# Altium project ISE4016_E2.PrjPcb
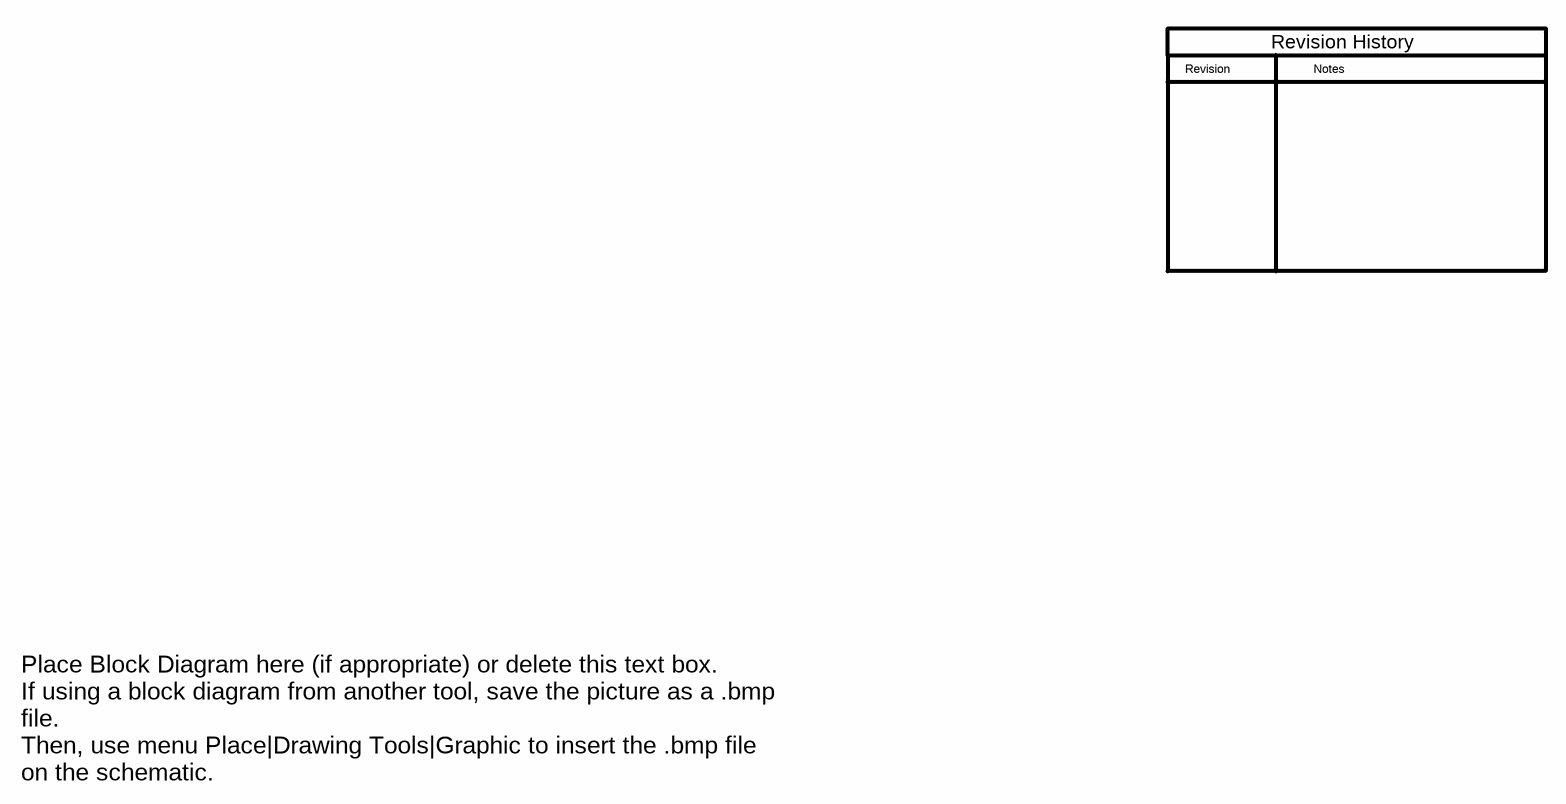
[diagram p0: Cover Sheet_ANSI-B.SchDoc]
TechSupport: http://www.ti.com/support; SCH_Rev: E2; PRJ_Title: ISE4016; PRJ_Number: ISE4016; PRJ_Engineer: Ajinder Singh; PRJ_Customer: Public Release; PCB_Rev: E2; PCB_Layout: Krypton Solutions; CopyrightYear: 2014
5 sheets, 111 parts. Net scope: global (net labels, ports and power ports of the same name join across sheets).
Board file: ISE4016_E2.PcbDoc
Sheets:
  Cover Sheet_ANSI-B.SchDoc
  BlankSheet_ANSI-B.SchDoc
  Hardware_ANSI-B.SchDoc
  Power.SchDoc
  Analog and EP.SchDoc

## Sheet Cover Sheet_ANSI-B.SchDoc
size 431 x 279 mm; Date: Not shown in title block; ApprovedBy: Not shown in title block; CheckedBy: Not shown in title block; Author: Not shown in title block; CompanyName: Not shown in title block; Engineer: Not shown in title block; Organization: Not shown in title block; Address1: Not shown in title block; Address2: Not shown in title block; Address3: Not shown in title block; Address4: Not shown in title block; DocumentNumber: 1; Revision: Use project parameter SCH_Rev; SheetNumber: 1; SheetTotal: 1; PageSetup: Record=PageOptions|CenterHorizontal=True|CenterVertical=True|PrintScale=1.00|XCorrection=1.00|YCorrection=1.00|PrintKind=0|BorderSize=5000000|LeftOffset=0|BottomOffset=0|Orientation=2|PaperLength=1000|PaperWidth=1000|Scale=100|PaperSource=15|PrintQuality=600|MediaType=1|DitherType=10|PaperKind=Letter|PrintScaleMode=1

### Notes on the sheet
- Revision
- Notes
- Revision History
- Place Block Diagram here (if appropriate) or delete this text box.
  If using a block diagram from another tool, save the picture as a .bmp file.
  Then, use menu Place|Drawing Tools|Graphic to insert the .bmp file on the schematic.

## Sheet BlankSheet_ANSI-B.SchDoc
size 431 x 279 mm; Date: Not shown in title block; ApprovedBy: Not shown in title block; CheckedBy: Not shown in title block; Author: Not shown in title block; CompanyName: Not shown in title block; Engineer: Not shown in title block; Organization: Not shown in title block; Address1: Not shown in title block; Address2: Not shown in title block; Address3: Not shown in title block; Address4: Not shown in title block; DocumentNumber: 1; Revision: Use project parameter SCH_Rev; SheetNumber: 1; SheetTotal: 1; PageSetup: Record=PageOptions|CenterHorizontal=True|CenterVertical=True|PrintScale=1.00|XCorrection=1.00|YCorrection=1.00|PrintKind=0|BorderSize=5000000|LeftOffset=0|BottomOffset=0|Orientation=2|PaperLength=1000|PaperWidth=1000|Scale=100|PaperSource=15|PrintQuality=600|MediaType=1|DitherType=10|PaperKind=Letter|PrintScaleMode=1

## Sheet Hardware_ANSI-B.SchDoc
size 431 x 279 mm; Date: Not shown in title block; ApprovedBy: Not shown in title block; CheckedBy: Not shown in title block; Author: Not shown in title block; CompanyName: Not shown in title block; Engineer: Not shown in title block; Organization: Not shown in title block; Address1: Not shown in title block; Address2: Not shown in title block; Address3: Not shown in title block; Address4: Not shown in title block; DocumentNumber: 1; Revision: Use project parameter SCH_Rev; SheetNumber: 1; SheetTotal: 1; PageSetup: Record=PageOptions|CenterHorizontal=True|CenterVertical=True|PrintScale=1.00|XCorrection=1.00|YCorrection=1.00|PrintKind=0|BorderSize=5000000|LeftOffset=0|BottomOffset=0|Orientation=2|PaperLength=1000|PaperWidth=1000|Scale=100|PaperSource=15|PrintQuality=600|MediaType=1|DitherType=10|PaperKind=Letter|PrintScaleMode=1
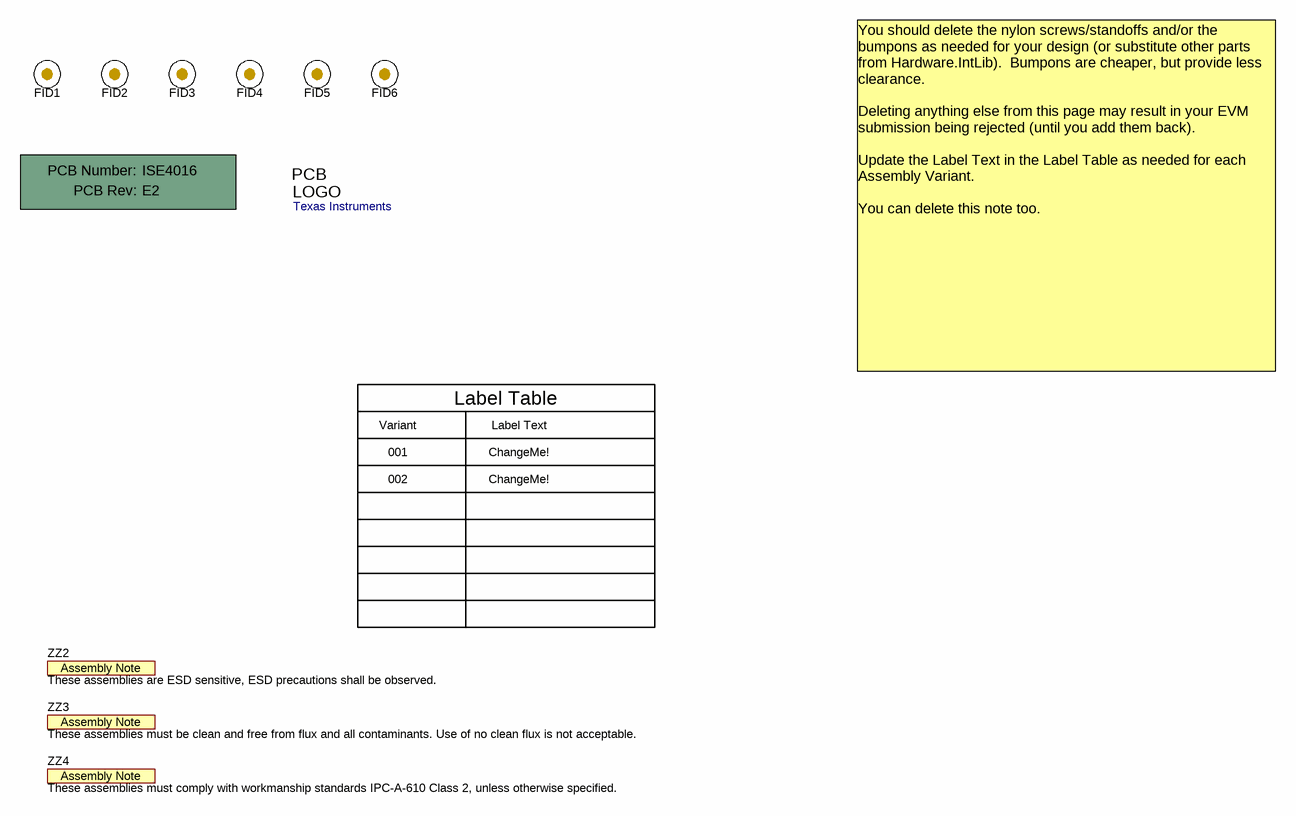
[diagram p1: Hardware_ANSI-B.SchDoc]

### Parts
!PCB1  Printed Circuit Board  (value not drawn)  (mechanical)
FID1  Fiducial  [Fiducial10-20]  (value not drawn)
FID2  Fiducial  [Fiducial10-20]  (value not drawn)
FID3  Fiducial  [Fiducial10-20]  (value not drawn)
FID4  Fiducial  [Fiducial10-20]  (value not drawn)
FID5  Fiducial  [Fiducial10-20]  (value not drawn)
FID6  Fiducial  [Fiducial10-20]  (value not drawn)
Logo1  Texas Instruments  [TI_Stacked_Overlay_Medium]  (no BOM)
ZZ2  These assemblies are ESD sensitive, ESD precautions shall be observed.  [AssemblyNote]  (no BOM)
ZZ3  These assemblies must be clean and free from flux and all contaminants. Use of no clean flux is not acceptable.  [AssemblyNote]  (no BOM)
ZZ4  These assemblies must comply with workmanship standards IPC-A-610 Class 2, unless otherwise specified.  [AssemblyNote]  (no BOM)

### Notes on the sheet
- Variant
- Label Table
- Label Text
- You should delete the nylon screws/standoffs and/or the bumpons as needed for your design (or substitute other parts from Hardware.IntLib).  Bumpons are cheaper, but provide less clearance.
  Deleting anything else from this page may result in your EVM submission being rejected (until you add them back).
  Update the Label Text in the Label Table as needed for each Assembly Variant.
  You can delete this note too.
- 001
- 002
- ChangeMe!

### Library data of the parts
!PCB1 = PCB: Manufacturer: Any; PartNumber: ISE4016; SymbolCreator: a0412235
FID1-FID6 = Fiducial: Fiducial mark.  There is nothing to buy or mount.; SymbolCreator: codlsc
Logo1 = TI_Logo: Texas Instrument Corporate Signature; SymbolCreator: a0412235
ZZ2-ZZ4 = AssemblyNote: SymbolCreator: codlsc

## Sheet Power.SchDoc
size 431 x 279 mm; Date: Not shown in title block; ApprovedBy: Not shown in title block; CheckedBy: Not shown in title block; Author: Not shown in title block; CompanyName: Not shown in title block; Engineer: Not shown in title block; Organization: Not shown in title block; Address1: Not shown in title block; Address2: Not shown in title block; Address3: Not shown in title block; Address4: Not shown in title block; DocumentNumber: 1; Revision: Use project parameter SCH_Rev; SheetNumber: 1; SheetTotal: 1; PageSetup: Record=PageOptions|CenterHorizontal=True|CenterVertical=True|PrintScale=0.96|XCorrection=1.00|YCorrection=1.00|PrintKind=0|BorderSize=5000000|LeftOffset=0|BottomOffset=0|Orientation=2|PaperLength=1000|PaperWidth=1000|Scale=100|PaperSource=15|PrintQuality=600|MediaType=1|DitherType=10|PaperKind=11x17|PrintScaleMode=1
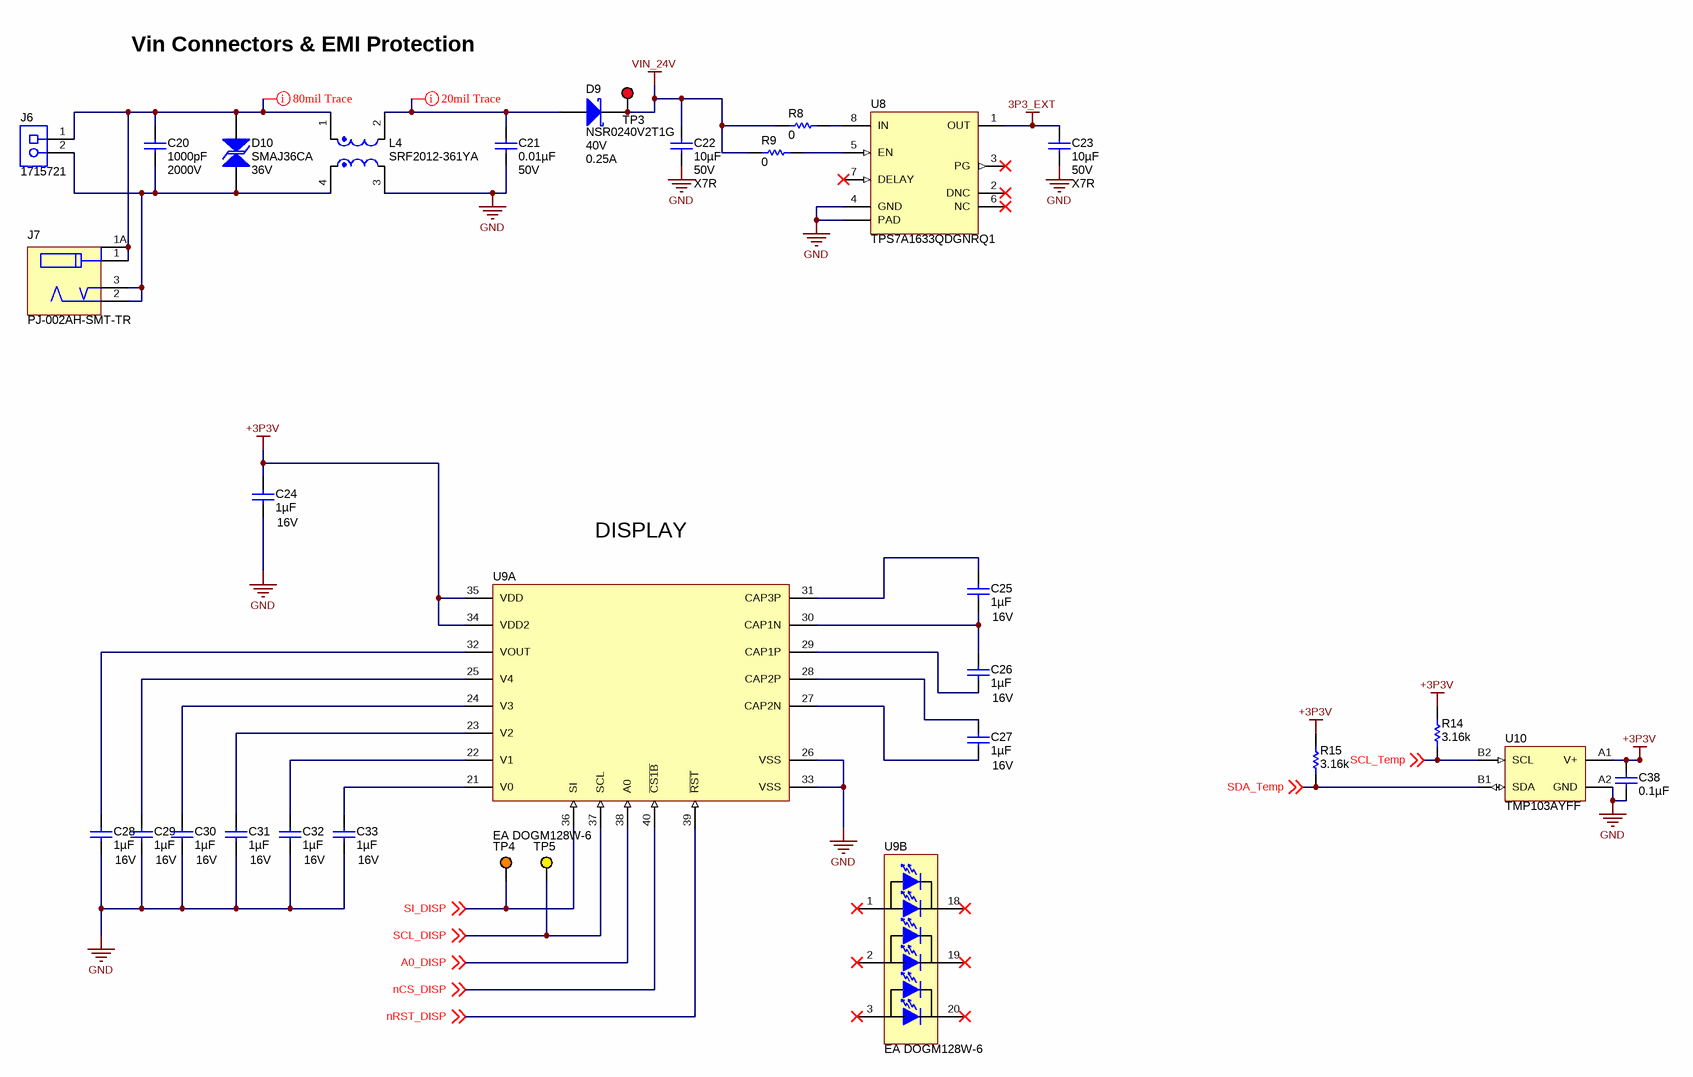
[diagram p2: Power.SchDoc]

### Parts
C20  ValueDisplayed: 1000pF  Value2: 2000V  [1210]  (hidden comment: C1210C102KGRACTU)
C21  ValueDisplayed: 0.01µF  Value2: 50V  [0402]  (hidden comment: GCM155R71H103KA55D)
C22  ValueDisplayed: 10µF  Value2: 50V  TempCo: X7R  [1210]  (hidden comment: GRM32ER71H106KA12L)
C23  ValueDisplayed: 10µF  Value2: 50V  TempCo: X7R  [1210]  (hidden comment: GRM32ER71H106KA12L)
C24  ValueDisplayed: 1µF  Value2: 16V  [0603]  (hidden comment: C1608X7R1C105K)
C25  ValueDisplayed: 1µF  Value2: 16V  [0603]  (hidden comment: C1608X7R1C105K)
C26  ValueDisplayed: 1µF  Value2: 16V  [0603]  (hidden comment: C1608X7R1C105K)
C27  ValueDisplayed: 1µF  Value2: 16V  [0603]  (hidden comment: C1608X7R1C105K)
C28  ValueDisplayed: 1µF  Value2: 16V  [0603]  (hidden comment: C1608X7R1C105K)
C29  ValueDisplayed: 1µF  Value2: 16V  [0603]  (hidden comment: C1608X7R1C105K)
C30  ValueDisplayed: 1µF  Value2: 16V  [0603]  (hidden comment: C1608X7R1C105K)
C31  ValueDisplayed: 1µF  Value2: 16V  [0603]  (hidden comment: C1608X7R1C105K)
C32  ValueDisplayed: 1µF  Value2: 16V  [0603]  (hidden comment: C1608X7R1C105K)
C33  ValueDisplayed: 1µF  Value2: 16V  [0603]  (hidden comment: C1608X7R1C105K)
C38  ValueDisplayed: 0.1µF  [0603]  (hidden comment: 06033C104JAT2A)
D9  NSR0240V2T1G  value 40V  Value1: 0.25A  [SOD-523]
D10  SMAJ36CA  value 36V  [SMA]
J6  1715721  [PhoenixContact_1715721]
J7  PJ-002AH-SMT-TR  [CUI_PJ-002AH-SMT]
L4  SRF2012-361YA  [SRF2012A]
R8  value 0  [0402]  (hidden comment: ERJ-2GE0R00X)
R9  value 0  [0402]  (hidden comment: ERJ-2GE0R00X)
R14  value 3.16k  [0603]  (hidden comment: CRCW06033K16FKEA)
R15  value 3.16k  [0603]  (hidden comment: CRCW06033K16FKEA)
TP3  5000  [Keystone5000]  (value not drawn)
TP4  5003  [Keystone5003]  (value not drawn)
TP5  5004  [Keystone5004]  (value not drawn)
U8  TPS7A1633QDGNRQ1  [DGN0008C_N]
U9  EA DOGM128W-6  [LCD-MODULE_EA DOGM128W-6]  (parts A,B of 2)
U10  TMP103AYFF  [YFF0004AAAA]

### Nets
3P3_EXT: C23.1 U8.1(OUT)
+3P3V: C24.1 C38.1 R14.2 R15.2 U9.34(VDD2) U9.35(VDD) U10.A1(V+)
GND: C21.2 C22.2 C23.2 C24.2 C28.2 C29.2 C30.2 C31.2 C32.2 C33.2 C38.2 L4.3 U8.4(GND) U8.9(PAD) U9.26(VSS) U9.33(VSS) U10.A2(GND)
VIN_24V: C22.1 D9.1(K) R8.1 R9.1 TP3.1
A0_DISP: U9.38(A0) ; off-sheet A0_DISP
nCS_DISP: U9.40(~{CS1B}) ; off-sheet nCS_DISP
nRST_DISP: U9.39(~{RST}) ; off-sheet nRST_DISP
SCL_DISP: TP5.1 U9.37(SCL) ; off-sheet SCL_DISP
SCL_Temp: R14.1 U10.B2(SCL) ; off-sheet SCL_Temp
SDA_Temp: R15.1 U10.B1(SDA) ; off-sheet SDA_Temp
SI_DISP: TP4.1 U9.36(SI) ; off-sheet SI_DISP
NetC20_1: C20.1 D10.2 J6.1 J7.1 J7.1A L4.1
NetC20_2: C20.2 D10.1 J6.2 J7.2 J7.3 L4.4
NetC21_1: C21.1 D9.2(A) L4.2
NetC25_1: C25.1 U9.31(CAP3P)
NetC25_2: C25.2 C26.1 U9.30(CAP1N)
NetC26_2: C26.2 U9.29(CAP1P)
NetC27_1: C27.1 U9.28(CAP2P)
NetC27_2: C27.2 U9.27(CAP2N)
NetC28_1: C28.1 U9.32(VOUT)
NetC29_1: C29.1 U9.25(V4)
NetC30_1: C30.1 U9.24(V3)
NetC31_1: C31.1 U9.23(V2)
NetC32_1: C32.1 U9.22(V1)
NetC33_1: C33.1 U9.21(V0)
NetR8_2: R8.2 U8.8(IN)
NetR9_2: R9.2 U8.5(EN)

Not connected (* = marked no-connect by the designer): U8 2(DNC)* 3(PG)* 6(NC)* 7(DELAY)*; U9 1(A)* 2(A)* 3(A)* 18(K)* 19(K)* 20(K)*

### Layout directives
rule Width Constraint [Pref Width = 80mil    Min Width = 80mil    Max Width = 80mil]: NetC20_1
rule Undefined; rule Width Constraint [Pref Width = 20mil    Min Width = 20mil    Max Width = 20mil]: NetC21_1

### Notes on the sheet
- Vin Connectors & EMI Protection
- DISPLAY

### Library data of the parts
C20 = C1210C102KGRACTU: CAP, CERM, 1000pF, 2000V, +/-10%, X7R, 1210; Manufacturer: Kemet; Polarized: N; CompType: Capacitor; U/M: EA; Cap_F: 0.000000001; Tolerance_%: 10; Value1: Unknown; VDC_V: 2000; TaMin_C: -55; TaMax_C: 125
C21 = GCM155R71H103KA55D: CAP, CERM, 0.01uF, 50V, +/-10%, C0G/NP0, 0402; Manufacturer: MuRata; Polarized: N; CompType: Capacitor; U/M: EA; Cap_F: 0.00000001; Tolerance_%: 10; Value1: Unknown; VDC_V: 50; TaMin_C: -55; TaMax_C: 125
C22 C23 = GRM32ER71H106KA12L: CAP, CERM, 10uF, 50V, +/-10%, X7R, 1210; Manufacturer: MuRata; Polarized: N; CompType: Capacitor; U/M: EA; Cap_F: 0.00001; Tolerance_%: 10; Value1: Unknown; VDC_V: 50; TaMin_C: -55; TaMax_C: 125
C24-C33 = C1608X7R1C105K: CAP, CERM, 1uF, 16V, +/-10%, X7R, 0603; Manufacturer: TDK; Polarized: N; CompType: Capacitor; U/M: EA; Cap_F: 0.000001; Tolerance_%: 10; ESR_Ohm: 0.0057; Value1: 0.0057 ohm; VDC_V: 16; TaMin_C: -55; TaMax_C: 125
C38 = 06033C104JAT2A: CAP, CERM, 0.1uF, 25V, +/-5%, X7R, 0603; Manufacturer: AVX; Polarized: N; CompType: Capacitor; U/M: EA; Cap_F: 0.0000001; Tolerance_%: 5; ESR_Ohm: 0.05; Value1: 0.05 ohm; VDC_V: 25; TaMin_C: -55; TaMax_C: 125
D9 = NSR0240V2T1G: Diode, Schottky, 40V, 0.25A, SOD-523; Manufacturer: ON Semiconductor; U/M: EA; Vf_V: 0.7; Value2: 0.7V; Io_A: 0.25; Vr_V: 40; TJmax_C: 150; RJC_CperW: 600
D10 = SMAJ36CA: Diode, TVS, Bi, 36V, 400W, SMA; Manufacturer: Littelfuse; U/M: EA; Power_W: 400; Vr_V: 36; RJA_CperW: 120
J6 = 1715721: Conn Term Block, 2POS, 5.08mm, TH; Manufacturer: Phoenix Contact; SymbolCreator: a0412235; Value: 2x1; CompType: Terminal Block; U/M: EA
J7 = PJ-002AH-SMT-TR: Power Jack, SMT; Manufacturer: CUI Inc.; SymbolCreator: a0411947; U/M: EA
L4 = SRF2012-361YA: Inductor, Wirewound, Ferrite, , 0.3A, 0.45 ohm, SMD; Manufacturer: Bourns; SymbolCreator: a0411947; Imax_A: 0.3; DCR_ohm: 0.45; ZTyp@100MHz_Ohm: 360; U/M: EA
R8 R9 = ERJ-2GE0R00X: RES, 0 ohm, 5%, 0.063W, 0402; Manufacturer: Panasonic; CompType: Resistor; Value_Code: 0000; Tolerance_%: 5; Power_W: 0.063; VDC_V: 50; TempCo: 600 ppm/C; EIA_Code: E24; U/M: EA
R14 R15 = CRCW06033K16FKEA: RES, 3.16k ohm, 1%, 0.1W, 0603; Manufacturer: Vishay-Dale; CompType: Resistor; Res_ohm: 3160; Value_Code: 3k16; Tolerance_%: 1; Power_W: 0.1; VDC_V: 75; TempCo: 100 ppm/C; EIA_Code: E96; U/M: EA
TP3 = 5000: Test Point, Miniature, Red, TH; Manufacturer: Keystone; CompType: Test Point Loop; U/M: EA
TP4 = 5003: Test Point, Miniature, Orange, TH; Manufacturer: Keystone; CompType: Test Point Loop; U/M: EA
TP5 = 5004: Test Point, Miniature, Yellow, TH; Manufacturer: Keystone; CompType: Test Point Loop; U/M: EA
U8 = TPS7A1633QDGNRQ1: 60-V, 5-µA IQ, 100-mA, Low-Dropout VOLTAGE REGULATOR With Enable and Power-Good, DGN0008C; Alternate Manufacturer: None; Manufacturer: Texas Instruments; SymbolCreator: a0411947; CompType: IC; U/M: EA
U9 = EA DOGM128W-6: Module, 128x64-pixel graphics display; Manufacturer: Electronic Assembly; SymbolCreator: a0799628
U10 = TMP103AYFF: Low-Power, Digital Temperature Sensor with Two-Wire Interface in WCSP, YFF0004AAAA; Alternate Manufacturer: None; Manufacturer: Texas Instruments; SymbolCreator: a0411947; CompType: IC; U/M: EA

## Sheet Analog and EP.SchDoc
size 431 x 279 mm; Date: Not shown in title block; ApprovedBy: Not shown in title block; CheckedBy: Not shown in title block; Author: Not shown in title block; CompanyName: Not shown in title block; Engineer: Not shown in title block; Organization: Not shown in title block; Address1: Not shown in title block; Address2: Not shown in title block; Address3: Not shown in title block; Address4: Not shown in title block; DocumentNumber: 1; Revision: Use project parameter SCH_Rev; SheetNumber: 1; SheetTotal: 1; PageSetup: Record=PageOptions|CenterHorizontal=True|CenterVertical=True|PrintScale=0.96|XCorrection=1.00|YCorrection=1.00|PrintKind=0|BorderSize=5000000|LeftOffset=0|BottomOffset=0|Orientation=2|PaperLength=1000|PaperWidth=1000|Scale=100|PaperSource=15|PrintQuality=600|MediaType=1|DitherType=10|PaperKind=11x17|PrintScaleMode=1
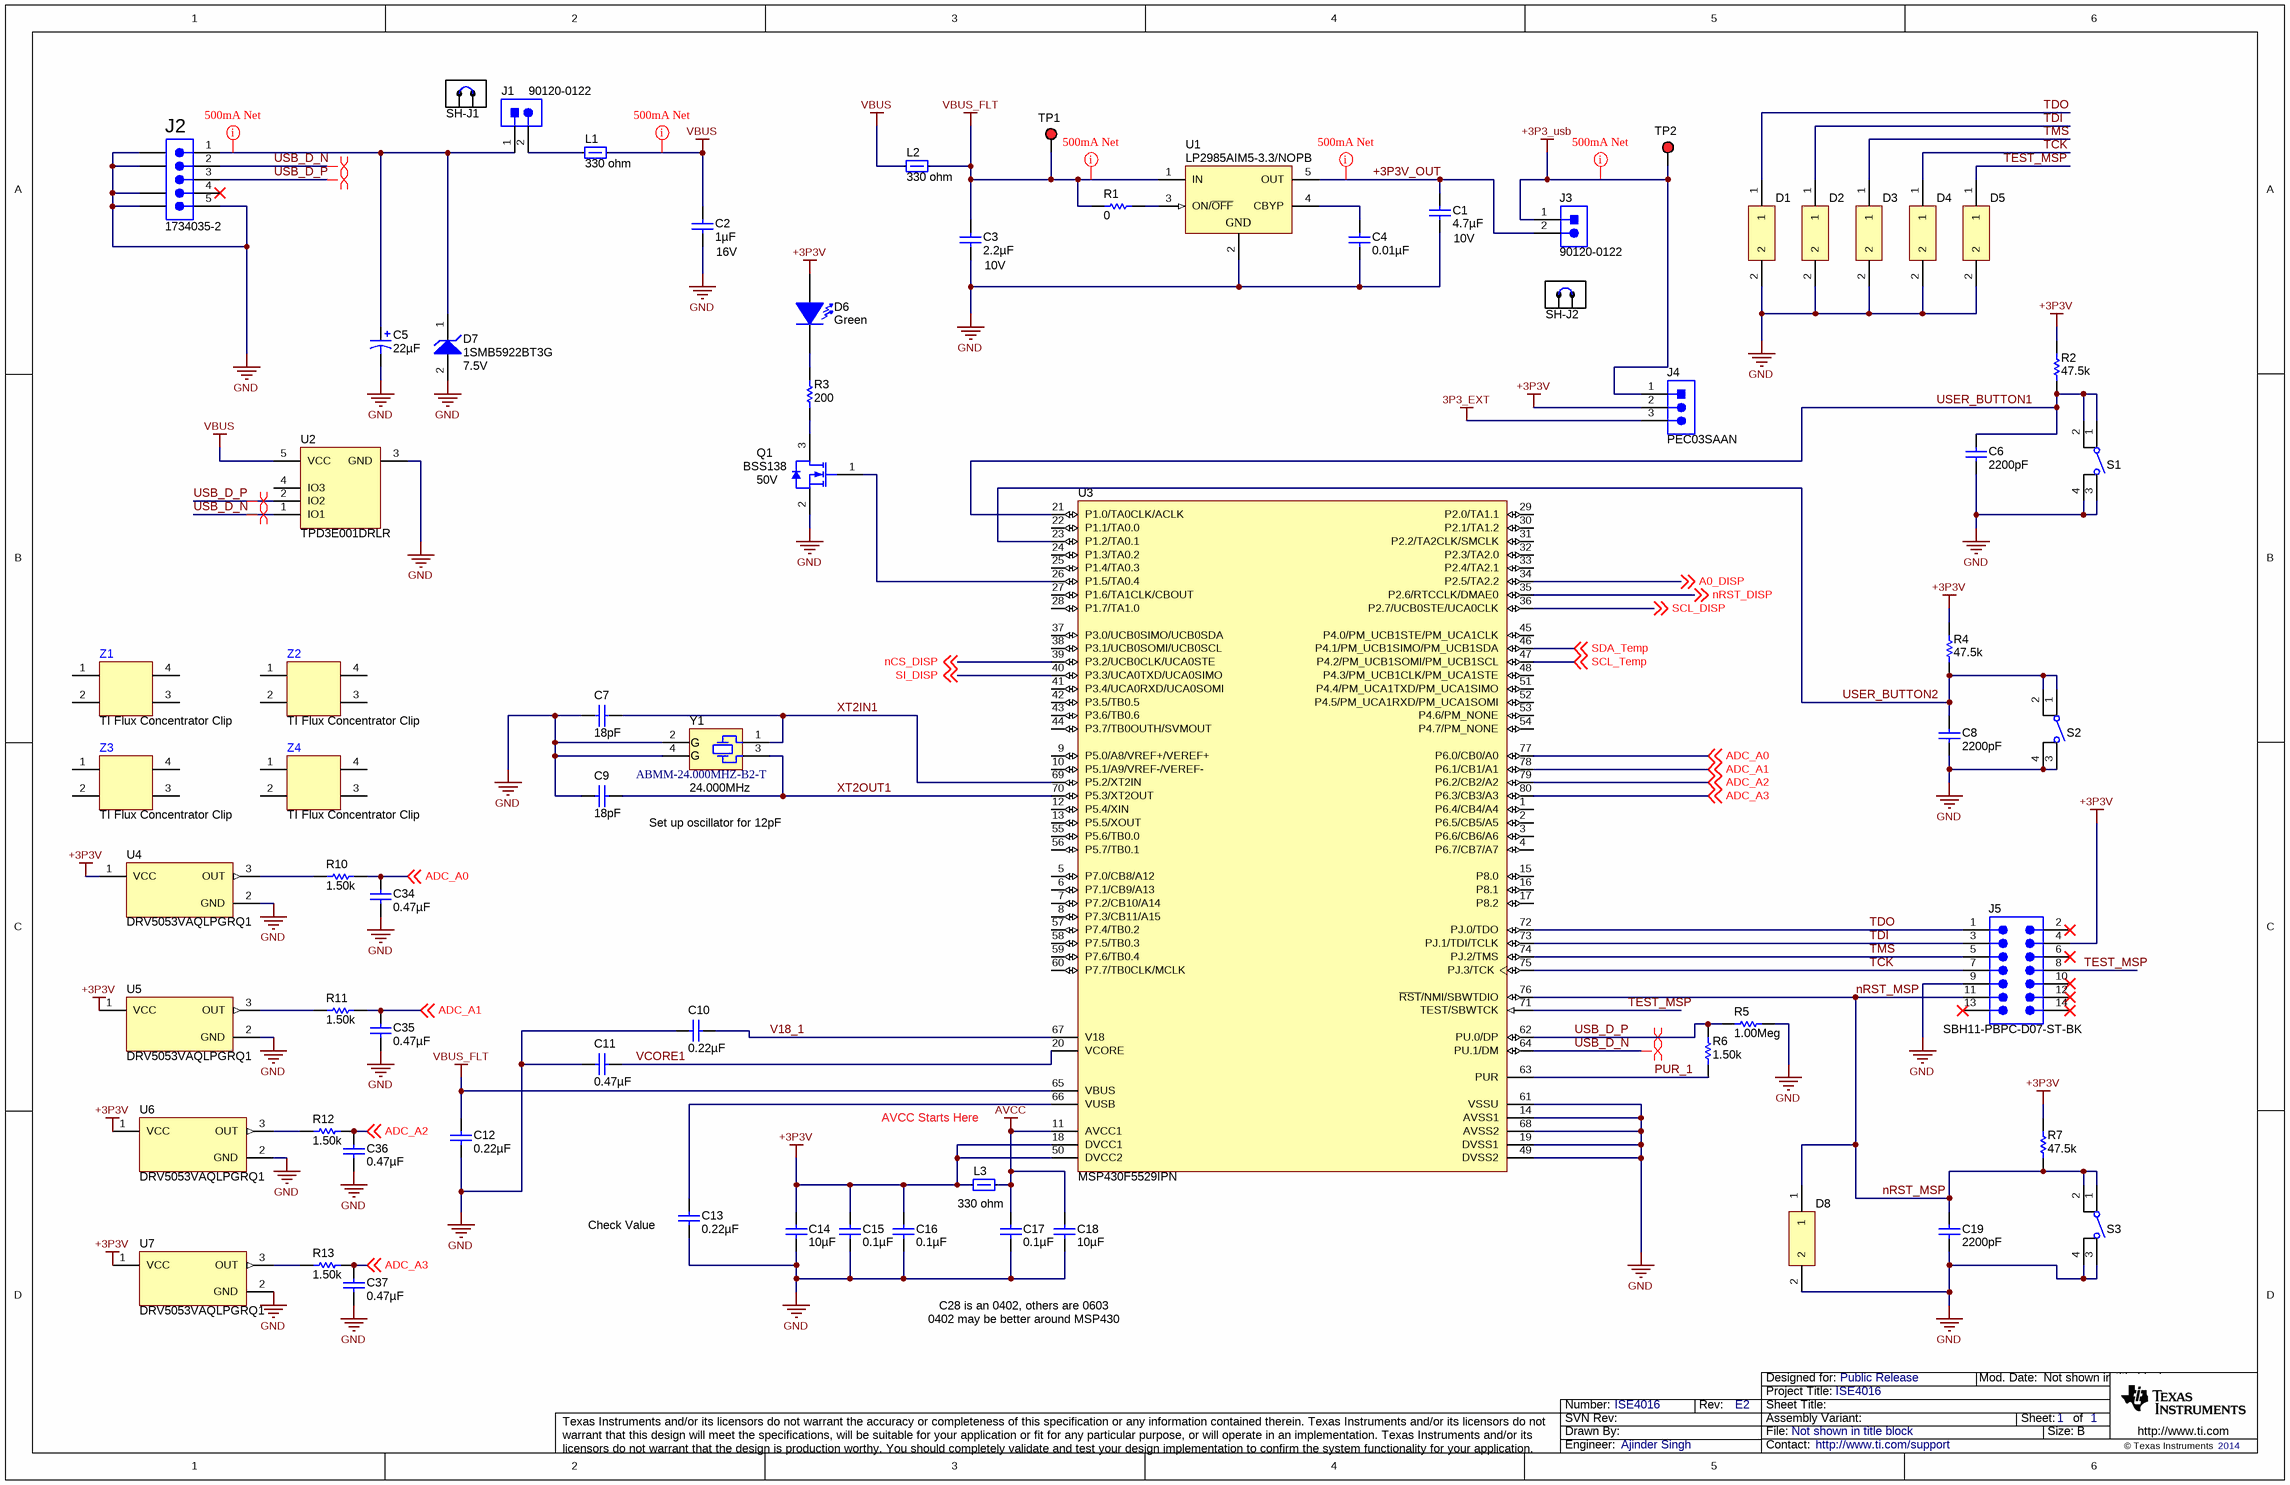
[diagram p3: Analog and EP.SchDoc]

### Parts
C1  ValueDisplayed: 4.7µF  Value2: 10V  [0805_HV]  (hidden comment: 0805ZD475KAT2A)
C2  ValueDisplayed: 1µF  Value2: 16V  [0603]  (hidden comment: C1608X7R1C105K)
C3  ValueDisplayed: 2.2µF  Value2: 10V  [0805_HV]  (hidden comment: C0805C225K8PACTU)
C4  ValueDisplayed: 0.01µF  [0402]  (hidden comment: GRM155R71C103KA01D)
C5  ValueDisplayed: 22µF  [CAPSMT_62_E55]  (hidden comment: EEE-1AA220WR)
C6  ValueDisplayed: 2200pF  [0603]  (hidden comment: 06031C222JAT2A)
C7  ValueDisplayed: 18pF  [0603]  (hidden comment: 06035A180JAT2A)
C8  ValueDisplayed: 2200pF  [0603]  (hidden comment: 06031C222JAT2A)
C9  ValueDisplayed: 18pF  [0603]  (hidden comment: 06035A180JAT2A)
C10  ValueDisplayed: 0.22µF  [0402L]  (hidden comment: GRM155R61A224KE19D)
C11  ValueDisplayed: 0.47µF  [0402]  (hidden comment: GRM155R61A474KE15D)
C12  ValueDisplayed: 0.22µF  [0402L]  (hidden comment: GRM155R61A224KE19D)
C13  ValueDisplayed: 0.22µF  [0402L]  (hidden comment: GRM155R61A224KE19D)
C14  ValueDisplayed: 10µF  [0805_HV]  (hidden comment: C0805C106K8PACTU)
C15  ValueDisplayed: 0.1µF  [0603]  (hidden comment: 06033C104JAT2A)
C16  ValueDisplayed: 0.1µF  [0603]  (hidden comment: 06033C104JAT2A)
C17  ValueDisplayed: 0.1µF  [0402]  (hidden comment: GRM155R61C104KA88D)
C18  ValueDisplayed: 10µF  [0805_HV]  (hidden comment: C0805C106K8PACTU)
C19  ValueDisplayed: 2200pF  [0603]  (hidden comment: 06031C222JAT2A)
C34  ValueDisplayed: 0.47µF  [0402]  (hidden comment: GRM155R61A474KE15D)
C35  ValueDisplayed: 0.47µF  [0402]  (hidden comment: GRM155R61A474KE15D)
C36  ValueDisplayed: 0.47µF  [0402]  (hidden comment: GRM155R61A474KE15D)
C37  ValueDisplayed: 0.47µF  [0402]  (hidden comment: GRM155R61A474KE15D)
D1  TPD1E10B06DPYR  [DPY0002A_N]  (value not drawn)
D2  TPD1E10B06DPYR  [DPY0002A_N]  (value not drawn)
D3  TPD1E10B06DPYR  [DPY0002A_N]  (value not drawn)
D4  TPD1E10B06DPYR  [DPY0002A_N]  (value not drawn)
D5  TPD1E10B06DPYR  [DPY0002A_N]  (value not drawn)
D6  value Green  [LED_LTST-C171]  (hidden comment: LTST-C190GKT)
D7  1SMB5922BT3G  value 7.5V  [SMB]
D8  TPD1E10B06DPYR  [DPY0002A_N]  (value not drawn)
J1  90120-0122  [CONN_90120-0122]
J2  1734035-2  [CONN_USB-Mini-B-1734035-2]
J3  90120-0122  [CONN_90120-0122]
J4  PEC03SAAN  [CONN_PEC03SAAN]
J5  SBH11-PBPC-D07-ST-BK  [CONN_SBH11-PBPC-D07-ST-BK]
L1  value 330 ohm  [0603]  (hidden comment: BLM18SG331TN1D)
L2  value 330 ohm  [0603]  (hidden comment: BLM18SG331TN1D)
L3  value 330 ohm  [0603]  (hidden comment: BLM18SG331TN1D)
Q1  BSS138  value 50V  [SOT-23]
R1  value 0  [0402]  (hidden comment: CRCW04020000Z0ED)
R2  value 47.5k  [0603]  (hidden comment: CRCW060347K5FKEA)
R3  value 200  [0603]  (hidden comment: CRCW0603200RJNEA)
R4  value 47.5k  [0603]  (hidden comment: CRCW060347K5FKEA)
R5  value 1.00Meg  [0402L]  (hidden comment: CRCW04021M00FKED)
R6  value 1.50k  [0402L]  (hidden comment: CRCW04021K50FKED)
R7  value 47.5k  [0603]  (hidden comment: CRCW060347K5FKEA)
R10  ValueDisplayed: 1.50k  [0402]  (hidden comment: CRCW04021K50FKED)
R11  ValueDisplayed: 1.50k  [0402]  (hidden comment: CRCW04021K50FKED)
R12  ValueDisplayed: 1.50k  [0402]  (hidden comment: CRCW04021K50FKED)
R13  ValueDisplayed: 1.50k  [0402]  (hidden comment: CRCW04021K50FKED)
S1  4-1437565-1  [SW_FSM4JSMA]  (value not drawn)
S2  4-1437565-1  [SW_FSM4JSMA]  (value not drawn)
S3  4-1437565-1  [SW_FSM4JSMA]  (value not drawn)
SH-J1  2SN-BK-G  [2SN-BK-G]  (value not drawn)
SH-J2  2SN-BK-G  [2SN-BK-G]  (value not drawn)
TP1  5000  [Keystone5000]  (value not drawn)
TP2  5000  [Keystone5000]  (value not drawn)
U1  LP2985AIM5-3.3/NOPB  [MF05A_N]
U2  TPD3E001DRLR  [DRL0005A]
U3  MSP430F5529IPN  [PN0080A_N]
U4  DRV5053VAQLPGRQ1  [LPG0003A]
U5  DRV5053VAQLPGRQ1  [LPG0003A]
U6  DRV5053VAQLPGRQ1  [LPG0003A]
U7  DRV5053VAQLPGRQ1  [LPG0003A]
Y1  ABMM-24.000MHZ-B2-T  Frequency: 24.000MHz  [Abracon_ABMM]
Z1  TI Flux Concentrator Clip  [TI Flux Concentrator Clip]
Z2  TI Flux Concentrator Clip  [TI Flux Concentrator Clip]
Z3  TI Flux Concentrator Clip  [TI Flux Concentrator Clip]
Z4  TI Flux Concentrator Clip  [TI Flux Concentrator Clip]

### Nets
3P3_EXT: J4.3
+3P3_usb: J3.1 J4.1 TP2.1
+3P3V: C14.1 C15.1 C16.1 D6.1(A) J4.2 J5.4 L3.1 R2.2 R4.2 R7.2 U3.18(DVCC1) U3.50(DVCC2) U4.1(VCC) U5.1(VCC) U6.1(VCC) U7.1(VCC)
AVCC: C17.1 C18.1 L3.2 U3.11(AVCC1)
GND: C1.2 C2.2 C3.2 C4.2 C5.2(-) C6.2 C7.2 C8.2 C9.2 C10.2 C11.2 C12.2 C13.2 C14.2 C15.2 C16.2 C17.2 C18.2 C19.2 C34.2 C35.2 C36.2 C37.2 D1.2 D2.2 D3.2 D4.2 D5.2 D7.2(A) D8.2 J2.5 J2.6(GND) J2.7(GND) J2.8(GND) J2.9(GND) J5.9 Q1.2(S) R5.2 S1.3 S1.4 S2.3 S2.4 S3.3 S3.4 U1.2(GND) U2.3(GND) U3.14(AVSS1) U3.19(DVSS1) U3.49(DVSS2) U3.61(VSSU) U3.68(AVSS2) U4.2(GND) U5.2(GND) U6.2(GND) U7.2(GND) Y1.2(GND) Y1.4(GND)
VBUS: C2.1 L1.2 L2.1 U2.5(VCC)
VBUS_FLT: C3.1 C12.1 L2.2 R1.2 TP1.1 U1.1(IN) U3.65(VBUS)
+3P3V_OUT: C1.1 J3.2 U1.5(OUT)
A0_DISP: U3.34(P2.5/TA2.2) ; off-sheet A0_DISP
ADC_A0: C34.1 R10.2 U3.77(P6.0/CB0/A0) ; off-sheet ADC_A0
ADC_A1: C35.1 R11.2 U3.78(P6.1/CB1/A1) ; off-sheet ADC_A1
ADC_A2: C36.1 R12.2 U3.79(P6.2/CB2/A2) ; off-sheet ADC_A2
ADC_A3: C37.1 R13.2 U3.80(P6.3/CB3/A3) ; off-sheet ADC_A3
nCS_DISP: U3.39(P3.2/UCB0CLK/UCA0STE) ; off-sheet nCS_DISP
nRST_DISP: U3.35(P2.6/RTCCLK/DMAE0) ; off-sheet nRST_DISP
nRST_MSP: C19.1 D8.1 J5.11 R7.1 S3.1 S3.2 U3.76(~{RST}/NMI/SBWTDIO)
PUR_1: R6.1 U3.63(PUR)
SCL_DISP: U3.36(P2.7/UCB0STE/UCA0CLK) ; off-sheet SCL_DISP
SCL_Temp: U3.47(P4.2/PM_UCB1SOMI/PM_UCB1SCL) ; off-sheet SCL_Temp
SDA_Temp: U3.46(P4.1/PM_UCB1SIMO/PM_UCB1SDA) ; off-sheet SDA_Temp
SI_DISP: U3.40(P3.3/UCA0TXD/UCA0SIMO) ; off-sheet SI_DISP
TCK: D4.1 J5.7 U3.75(PJ.3/TCK)
TDI: D2.1 J5.3 U3.73(PJ.1/TDI/TCLK)
TDO: D1.1 J5.1 U3.72(PJ.0/TDO)
TEST_MSP: D5.1 J5.8 U3.71(TEST/SBWTCK)
TMS: D3.1 J5.5 U3.74(PJ.2/TMS)
USB_D_N: J2.2 U2.1(IO1) U3.64(PU.1/DM)
USB_D_P: J2.3 R5.1 R6.2 U2.2(IO2) U3.62(PU.0/DP)
USER_BUTTON1: C6.1 R2.1 S1.1 S1.2 U3.21(P1.0/TA0CLK/ACLK)
USER_BUTTON2: C8.1 R4.1 S2.1 S2.2 U3.23(P1.2/TA0.1)
V18_1: C10.1 U3.67(V18)
VCORE1: C11.1 U3.20(VCORE)
XT2IN1: C7.1 U3.69(P5.2/XT2IN) Y1.1
XT2OUT1: C9.1 U3.70(P5.3/XT2OUT) Y1.3
NetC4_1: C4.1 U1.4(CBYP)
NetC5_1: C5.1(+) D7.1(K) J1.1 J2.1
NetC13_1: C13.1 U3.66(VUSB)
NetD6_2: D6.2(K) R3.2
NetJ1_2: J1.2 L1.1
NetQ1_1: Q1.1(G) U3.26(P1.5/TA0.4)
NetQ1_3: Q1.3(D) R3.1
NetR1_1: R1.1 U1.3(ON/~{OFF})
NetR10_1: R10.1 U4.3(OUT)
NetR11_1: R11.1 U5.3(OUT)
NetR12_1: R12.1 U6.3(OUT)
NetR13_1: R13.1 U7.3(OUT)

Not connected (* = marked no-connect by the designer): J2 4*; J5 2* 6* 10* 12* 13* 14*; U2 4(IO3); U3 1(P6.4/CB4/A4) 2(P6.5/CB5/A5) 3(P6.6/CB6/A6) 4(P6.7/CB7/A7) 5(P7.0/CB8/A12) 6(P7.1/CB9/A13) 7(P7.2/CB10/A14) 8(P7.3/CB11/A15) 9(P5.0/A8/VREF+/VEREF+) 10(P5.1/A9/VREF-/VEREF-) 12(P5.4/XIN) 13(P5.5/XOUT) 15(P8.0) 16(P8.1) 17(P8.2) 22(P1.1/TA0.0) 24(P1.3/TA0.2) 25(P1.4/TA0.3) 27(P1.6/TA1CLK/CBOUT) 28(P1.7/TA1.0) 29(P2.0/TA1.1) 30(P2.1/TA1.2) 31(P2.2/TA2CLK/SMCLK) 32(P2.3/TA2.0) 33(P2.4/TA2.1) 37(P3.0/UCB0SIMO/UCB0SDA) 38(P3.1/UCB0SOMI/UCB0SCL) 41(P3.4/UCA0RXD/UCA0SOMI) 42(P3.5/TB0.5) 43(P3.6/TB0.6) 44(P3.7/TB0OUTH/SVMOUT) 45(P4.0/PM_UCB1STE/PM_UCA1CLK) 48(P4.3/PM_UCB1CLK/PM_UCA1STE) 51(P4.4/PM_UCA1TXD/PM_UCA1SIMO) 52(P4.5/PM_UCA1RXD/PM_UCA1SOMI) 53(P4.6/PM_NONE) 54(P4.7/PM_NONE) 55(P5.6/TB0.0) 56(P5.7/TB0.1) 57(P7.4/TB0.2) 58(P7.5/TB0.3) 59(P7.6/TB0.4) 60(P7.7/TB0CLK/MCLK); Z1 1 2 3 4; Z2 1 2 3 4; Z3 1 2 3 4; Z4 1 2 3 4

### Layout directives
rule Width Constraint [Pref Width = 25mil    Min Width = 5mil    Max Width = 100mil]: +3P3_usb, +3P3V_OUT, NetC5_1, VBUS, VBUS_FLT
differential pair: USB_D_N, USB_D_P

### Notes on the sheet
- (near C9) Set up oscillator for 12pF
- AVCC Starts Here
- (near C13) Check Value
- C28 is an 0402, others are 0603
- 0402 may be better around MSP430

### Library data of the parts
C1 = 0805ZD475KAT2A: CAP, CERM, 4.7uF, 10V, +/-10%, X5R, 0805; Manufacturer: AVX; Polarized: N; CompType: Capacitor; U/M: EA; Cap_F: 0.0000047; Tolerance_%: 10; ESR_Ohm: 0.007; Value1: 0.007 ohm; TaMin_C: -55; TaMax_C: 85; Cap_Case: 0805
C2 = C1608X7R1C105K: as C24 on sheet Power
C3 = C0805C225K8PACTU: CAP, CERM, 2.2uF, 10V, +/-10%, X5R, 0805; Manufacturer: Kemet; Polarized: N; CompType: Capacitor; U/M: EA; Cap_F: 0.0000022; Tolerance_%: 10; ESR_Ohm: 0.006; Value1: 0.006 ohm; IRMS_A: 7.32; TaMin_C: -55; TaMax_C: 85; Cap_Case: 0805
C4 = GRM155R71C103KA01D: CAP, CERM, 0.01uF, 16V, +/-10%, X7R, 0402; Manufacturer: MuRata; Polarized: N; CompType: Capacitor; U/M: EA; Cap_F: 0.00000001; Tolerance_%: 10; Value1: Unknown; VDC_V: 16; TaMin_C: -55; TaMax_C: 125
C5 = EMVE100ADA220ME55G: CAP ALUM 22UF 10V 20% SMD; Manufacturer: Panasonic - ECG; Polarized: Y; CompType: Capacitor; U/M: EA; Cap_F: 0.000022; Tolerance_%: 20; VDC_V: 10; IRMS_A: 0.03; TaMin_C: -40; TaMax_C: 105; Cap_Case: E55
C6 C8 C19 = 06031C222JAT2A: CAP, CERM, 2200pF, 100V, +/-5%, X7R, 0603; Manufacturer: AVX; Polarized: N; CompType: Capacitor; U/M: EA; Cap_F: 0.0000000022; Tolerance_%: 5; ESR_Ohm: 0.192; Value1: 0.192 ohm; VDC_V: 100; TaMin_C: -55; TaMax_C: 125
C7 C9 = 06035A180JAT2A: CAP, CERM, 18pF, 50V, +/-5%, C0G/NP0, 0603; Manufacturer: AVX; Polarized: N; CompType: Capacitor; U/M: EA; Cap_F: 0.000000000018; Tolerance_%: 5; ESR_Ohm: 0.289; Value1: 0.289 ohm; VDC_V: 50; TaMin_C: -55; TaMax_C: 125
C10 C12 C13 = GRM155R61A224KE19D: CAP, CERM, 0.22uF, 10V, +/-10%, X5R, 0402; Manufacturer: MuRata; Polarized: N; CompType: Capacitor; U/M: EA; Cap_F: 0.00000022; Tolerance_%: 10; Value1: Unknown; TaMin_C: -55; TaMax_C: 85; Cap_Case: 0402
C11 C34-C37 = GRM155R61A474KE15D: CAP, CERM, 0.47uF, 10V, +/-10%, X5R, 0402; Manufacturer: MuRata; Polarized: N; CompType: Capacitor; U/M: EA; Cap_F: 0.00000047; Tolerance_%: 10; Value1: Unknown; TaMin_C: -55; TaMax_C: 85
C14 C18 = C0805C106K8PACTU: CAP, CERM, 10uF, 10V, +/-10%, X5R, 0805; Manufacturer: Kemet; Polarized: N; CompType: Capacitor; U/M: EA; Cap_F: 0.00001; Tolerance_%: 10; ESR_Ohm: 0.003; Value1: 0.003 ohm; IRMS_A: 11.43; TaMin_C: -55; TaMax_C: 85; Cap_Case: 0805
C15 C16 = 06033C104JAT2A: as C38 on sheet Power
C17 = GRM155R61C104KA88D: CAP, CERM, 0.1uF, 16V, +/-10%, X5R, 0402; Manufacturer: MuRata; Polarized: N; CompType: Capacitor; U/M: EA; Cap_F: 0.0000001; Tolerance_%: 10; Value1: Unknown; VDC_V: 16; TaMin_C: -55; TaMax_C: 85
D1-D5 D8 = TPD1E10B06DPYR: ESD in 0402 Package with 10 pF Capacitance and 6 V Breakdown, 1 Channel, -40 to +125 degC, 2-pin X2SON (DPY), Green (RoHS & no Sb/Br); Manufacturer: Texas Instruments; Alternate Manufacturer: None; Alternate PartNumber: Equivalent; Breakdown Voltage(Min)(V): 6; Eco-Plan: TBD; IEC 61000-4-2 Air-Gap(+/- kV): 30; IO Capacitance(Typ)(pF): 10; SubFamily: ESD Solution
D6 = LTST-C190GKT: LED, Green, SMD; Manufacturer: Lite-On; Vf_V: 2.1; Value2: 2.1V; Io_A: 0.02; Power_TotalModule: 0.1; Value1: 0.1W; U/M: EA
D7 = 1SMB5922BT3G: Diode, Zener, 7.5V, 550mW, SMB; Manufacturer: ON Semiconductor; U/M: EA; Power_W: 0.55; Vz_V: 7.5; Value1: 0.55W; RJA_CperW: 226
J1 J3 = 90120-0122: Header, 100mil, 2x1, Tin plated, TH; Manufacturer: Molex; SymbolCreator: a0412235; U/M: EA
J2 = 1734035-2: Connector, Receptacle, Mini-USB Type B, R/A, Top Mount SMT; Manufacturer: TE Connectivity; SymbolCreator: A0412235; U/M: EA
J4 = PEC03SAAN: Header, 100mil, 3x1, Tin plated, TH; Manufacturer: Sullins Connector Solutions; SymbolCreator: a0799628; U/M: EA
J5 = SBH11-PBPC-D07-ST-BK: Header (shrouded), 100 mil, 7x2, Gold plated, TH; Manufacturer: Sullins Connector Solutions; SymbolCreator: a0412235; CompType: Connector; U/M: EA
L1-L3 = BLM18SG331TN1D: 1.5A Ferrite Bead, 330 ohm @ 100MHz, SMD; Manufacturer: MuRata; Imax_A: 1.5; DCR_ohm: 0.07; Value1: 0.07 ohm; ZTyp@100MHz_Ohm: 330; U/M: EA
Q1 = BSS138: MOSFET, N-CH, 50V, 0.22A, SOT-23; Manufacturer: Fairchild Semiconductor; Alternate Manufacturer: None; U/M: EA; ChType: N; VdsMax_V: 50; Value1: 6 ohm; Rdson45_Ohm: 6; Value2: 1.7 nC; QgTyp_nC: 1.7; Vgs_V: 20; IdsMax_A: 0.22
R1 = CRCW04020000Z0ED: RES, 0 ohm, 5%, 0.063W, 0402; Manufacturer: Vishay-Dale; CompType: Resistor; Value_Code: 0000; Tolerance_%: 5; Power_W: 0.063; VDC_V: 50; TempCo: 200 ppm/C; EIA_Code: E24; U/M: EA
R2 R4 R7 = CRCW060347K5FKEA: RES, 47.5k ohm, 1%, 0.1W, 0603; Manufacturer: Vishay-Dale; CompType: Resistor; Res_ohm: 47500; Value_Code: 47k5; Tolerance_%: 1; Power_W: 0.1; VDC_V: 75; TempCo: 100 ppm/C; EIA_Code: E96; U/M: EA
R3 = CRCW0603200RJNEA: RES, 200 ohm, 5%, 0.1W, 0603; Manufacturer: Vishay-Dale; CompType: Resistor; Value_Code: 200R; Tolerance_%: 5; Power_W: 0.1; VDC_V: 75; TempCo: 200 ppm/C; EIA_Code: E24; U/M: EA
R5 = CRCW04021M00FKED: RES, 1.00Meg ohm, 1%, 0.063W, 0402; Manufacturer: Vishay-Dale; CompType: Resistor; Res_ohm: 1000000; Value_Code: 1M00; Tolerance_%: 1; Power_W: 0.063; VDC_V: 50; TempCo: 100 ppm/C; EIA_Code: E96; U/M: EA
R6 = CRCW04021K50FKED: RES, 1.50k ohm, 1%, 0.063W, 0402; Manufacturer: Vishay-Dale; CompType: Resistor; Res_ohm: 1500; Value_Code: 1k50; Tolerance_%: 1; Power_W: 0.063; VDC_V: 50; TempCo: 100 ppm/C; EIA_Code: E96; U/M: EA
R10-R13 = CRCW04021K50FKED: RES, 1.50 k, 1%, 0.063 W, 0402; Manufacturer: Vishay-Dale; CompType: Resistor; Res_ohm: 1500; Value: 1.50k; Value_Code: 1k50; Tolerance_%: 1; Power_W: 0.063; Value2: 0.063W; VDC_V: 50; TempCo: 100 ppm/C; EIA_Code: E96; U/M: EA
S1-S3 = 4-1437565-1: Switch, Tactile, SPST-NO, 0.05A, 12V, SMT; Manufacturer: TE Connectivity; SymbolCreator: a0412235; VDC_V: 12; SwitchFunction: Off-Mom; PositionCount: 1; CurrentRating_mA: 50
SH-J1 SH-J2 = 2SN-BK-G: Shunt, 2mm, Gold plated, Black; Manufacturer: Samtec; Value: 1x2; Note: You can "mate" this to a header by matching the designator.  i.e. use SH-J3 for header J3
TP1 TP2 = 5000: as TP3 on sheet Power
U1 = LP2985AIM5-3.3/NOPB: Micropower 150 mA Low-Noise Ultra Low-Dropout Regulator, 5-pin SOT-23, Pb-Free; Manufacturer: National Semiconductor; PackageTopMarking: L0RA*XTT; PowerWise: N; CompType: LDO IC
U2 = TPD3E001DRLR: Low-Capacitance + / - 15 kV ESD-Protection Array for High-Speed Data Interfaces, 3 Channels, -40 to +85 degC, 5-pin SOT (DRL), Green (RoHS & no Sb/Br); Manufacturer: Texas Instruments; Alternate Manufacturer: None; Alternate PartNumber: Equivalent; Breakdown Voltage(Min)(V): 11; IEC 61000-4-2 Air-Gap(+/- kV): 15; IEC 61000-4-2 Contact(+/- kV): 8; IO Capacitance(Typ)(pF): 1.5; IO Leakage Current(nA): 1; SubFamily: ESD Solution; USB High Speed: TRUE
U3 = MSP430F5529IPN: Mixed Signal MicroController, PN0080A; Alternate Manufacturer: None; Manufacturer: Texas Instruments; ADC: 12-bit SAR; ADC Channels: 16; Brown Out Reset: Yes; DMA: 3; Eco-Plan: Green (RoHS & no Sb/Br); Flash(KB): 128; Frequency(MHz): 25; GPIO: 63; Multiplier: 32x32; SRAM(B): 8192; SubFamily: 5 Series; Timers - 16-bit: 4; USB: 1; USCI_A (UART/LIN/IrDA/SPI): 2; SymbolCreator: Altium/a0412235; CompType: IC; U/M: EA
U4-U7 = DRV5053VAQLPGRQ1: Analog Linear Hall -80 mV/mt-40 - 125°C, LPG0003A; Alternate Manufacturer: None; Manufacturer: Texas Instruments; SymbolCreator: a0799628; CompType: IC; U/M: EA
Y1 = ABMM-24.000MHZ-B2-T: Crystal, 24.000MHz, 18pF, SMD; Manufacturer: Abracon Corportation; SymbolCreator: a0412235; U/M: EA; TaMin_C: -20; TaMax_C: 70; Frequency Stability: ±50ppm
Z1-Z4 = TI Flux Concentrator Clip: Manufacturer: Produkt Works

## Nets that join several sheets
3P3_EXT: Power (C23.1 U8.1), Analog and EP (J4.3)
+3P3V: Power (7 pins), Analog and EP (16 pins)
GND: Power (17 pins), Analog and EP (57 pins)
A0_DISP: Power (U9.38), Analog and EP (U3.34)
nCS_DISP: Power (U9.40), Analog and EP (U3.39)
nRST_DISP: Power (U9.39), Analog and EP (U3.35)
SCL_DISP: Power (TP5.1 U9.37), Analog and EP (U3.36)
SCL_Temp: Power (R14.1 U10.B2), Analog and EP (U3.47)
SDA_Temp: Power (R15.1 U10.B1), Analog and EP (U3.46)
SI_DISP: Power (TP4.1 U9.36), Analog and EP (U3.40)

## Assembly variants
001: not fitted FID1 FID2 FID3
